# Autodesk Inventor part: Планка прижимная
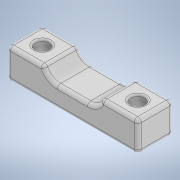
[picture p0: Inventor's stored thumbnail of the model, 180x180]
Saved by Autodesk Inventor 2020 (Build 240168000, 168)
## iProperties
Created: 2023-11
Part Number: Планка прижимная
Material: Типовые
Document SubType Name: Modeling
Designer: User
Density: 1 g/cm^3
Appearance: По умолчанию
Author: User
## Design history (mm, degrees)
sketch "Эскиз1"
  geometry: L1 (18.5, 3.5)-(18.5, -5); L2 (18.5, -5)-(-18.5, -5); L3 (-18.5, -5)-(-18.5, 3.5); L4 (4.25, -5)-(-4.25, -5); L5 (-4.25, 0.75)-(4.25, 0.75); L6 (-18.5, 3.5)-(-8.226, 3.5); L7 (8.226, 3.5)-(18.5, 3.5); A1 r 4.25 centre (-4.25, 5) between (-8.226, 3.5) and (-4.25, 0.75); A2 r 4.25 centre (4.25, 5) between (4.25, 0.75) and (8.226, 3.5); 1 further point
  constraints: 14 end point, 4 point on circle, 2 centre point, 2 point on line, 1 parallel
extrude "Выдавливание1" new body sketch "Эскиз1" distance "d8" = 10; taper "d9" = 0 deg
sketch "Эскиз2"
  geometry: C1 r 2 at (5, -5); C2 r 2 at (32, -5); 1 further point
  constraints: 2 centre point
extrude "Выдавливание2" cut sketch "Эскиз2" distance "d12" = 10; taper "d13" = 0 deg
fillet "Сопряжение1" dims "d14" = 1
fillet "Сопряжение2" dims "d15" = 0.5
node "Твердое тело1"
